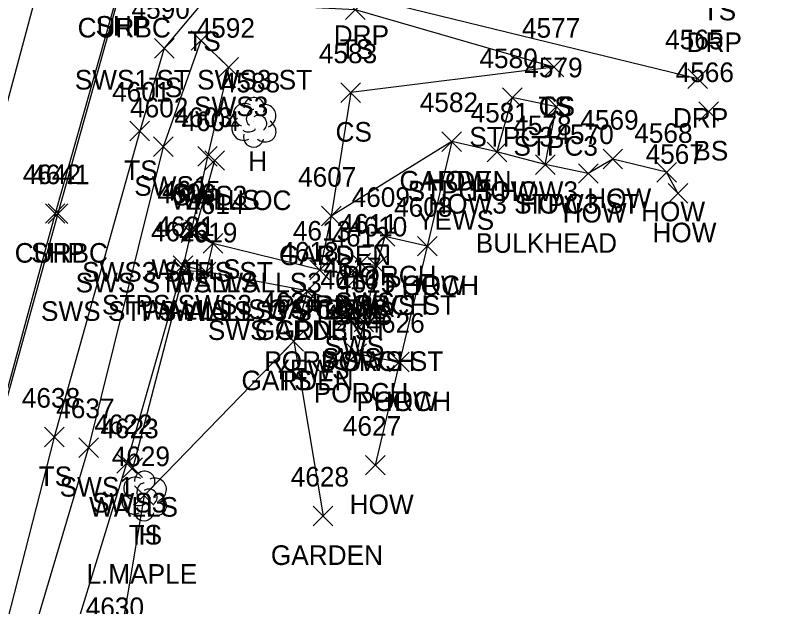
# Model space of a CAD drawing. Extents: x 1443912 to 1445411, y 621446 to 623693.
# Drawn here: x 1444910.4 to 1444988.1, y 623071.7 to 623132 of the extents above; entities that cross this region are included whole.
import ezdxf

# ---------------------------------------------------------------- set-up
doc = ezdxf.new("R2010")
doc.units = 0
for name, color, linetype in [('L_A', 7, 'Continuous'), ('L_C', 7, 'Continuous'), ('L_I', 7, 'Continuous'), ('L_TIC', 7, 'Continuous'), ('LAPB', 7, 'Continuous'), ('LBC', 7, 'Continuous'), ('LBF', 7, 'Continuous'), ('LELB', 7, 'Continuous'), ('LTD', 7, 'Continuous'), ('LWS', 7, 'Continuous'), ('P_A', 7, 'Continuous'), ('P_I', 7, 'Continuous'), ('P_TIC', 7, 'Continuous'), ('PET', 7, 'Continuous'), ('PSP', 7, 'Continuous'), ('R_A', 7, 'Continuous'), ('R_C', 7, 'Continuous'), ('R_I', 7, 'Continuous'), ('R_TIC', 7, 'Continuous'), ('RC', 7, 'Continuous'), ('RDP', 7, 'Continuous'), ('RSW', 7, 'Continuous')]:
    doc.layers.add(name, color=color, linetype=linetype)

msp = doc.modelspace()

# ---------------------------------------------------------------- linework, layer by layer
at = {"layer": 'L_TIC'}
for points in [[(1444944.131, 623131.561), (1444946.131, 623133.561)], [(1444946.131, 623131.561), (1444944.131, 623133.561)], [(1444924.638, 623127.642), (1444926.638, 623129.642)], [(1444926.638, 623127.642), (1444924.638, 623129.642)], [(1444964.389, 623125.715), (1444966.389, 623127.715)], [(1444966.389, 623125.715), (1444964.389, 623127.715)], [(1444964.389, 623125.715), (1444966.389, 623127.715)], [(1444966.389, 623125.715), (1444964.389, 623127.715)], [(1444943.665, 623123.111), (1444945.665, 623125.111)], [(1444945.665, 623123.111), (1444943.665, 623125.111)], [(1444943.665, 623123.111), (1444945.665, 623125.111)], [(1444945.665, 623123.111), (1444943.665, 623125.111)], [(1444960.138, 623122.61), (1444962.138, 623124.61)], [(1444962.138, 623122.61), (1444960.138, 623124.61)], [(1444964.641, 623121.674), (1444966.641, 623123.674)], [(1444966.641, 623121.674), (1444964.641, 623123.674)], [(1444980.176, 623121.189), (1444982.176, 623123.189)], [(1444982.176, 623121.189), (1444980.176, 623123.189)], [(1444922.129, 623119.197), (1444924.129, 623121.197)], [(1444924.129, 623119.197), (1444922.129, 623121.197)], [(1444953.963, 623118.122), (1444955.963, 623120.122)], [(1444955.963, 623118.122), (1444953.963, 623120.122)], [(1444953.963, 623118.122), (1444955.963, 623120.122)], [(1444955.963, 623118.122), (1444953.963, 623120.122)], [(1444958.58, 623117.065), (1444960.58, 623119.065)], [(1444960.58, 623117.065), (1444958.58, 623119.065)], [(1444958.58, 623117.065), (1444960.58, 623119.065)], [(1444960.58, 623117.065), (1444958.58, 623119.065)], [(1444929.77, 623116.189), (1444931.77, 623118.189)], [(1444931.77, 623116.189), (1444929.77, 623118.189)], [(1444970.402, 623116.333), (1444972.402, 623118.333)], [(1444972.402, 623116.333), (1444970.402, 623118.333)], [(1444963.508, 623115.772), (1444965.508, 623117.772)], [(1444965.508, 623115.772), (1444963.508, 623117.772)], [(1444963.508, 623115.772), (1444965.508, 623117.772)], [(1444965.508, 623115.772), (1444963.508, 623117.772)], [(1444967.895, 623114.862), (1444969.895, 623116.862)], [(1444969.895, 623114.862), (1444967.895, 623116.862)], [(1444975.896, 623114.984), (1444977.896, 623116.984)], [(1444977.896, 623114.984), (1444975.896, 623116.984)], [(1444977.054, 623112.845), (1444979.054, 623114.845)], [(1444979.054, 623112.845), (1444977.054, 623114.845)], [(1444941.67, 623110.518), (1444943.67, 623112.518)], [(1444943.67, 623110.518), (1444941.67, 623112.518)], [(1444941.67, 623110.518), (1444943.67, 623112.518)], [(1444943.67, 623110.518), (1444941.67, 623112.518)], [(1444927.357, 623108.831), (1444929.357, 623110.831)], [(1444929.357, 623108.831), (1444927.357, 623110.831)], [(1444927.79, 623109.107), (1444929.79, 623111.107)], [(1444929.79, 623109.107), (1444927.79, 623111.107)], [(1444947.143, 623108.453), (1444949.143, 623110.453)], [(1444949.143, 623108.453), (1444947.143, 623110.453)], [(1444929.602, 623107.733), (1444931.602, 623109.733)], [(1444931.602, 623107.733), (1444929.602, 623109.733)], [(1444929.602, 623107.733), (1444931.602, 623109.733)], [(1444931.602, 623107.733), (1444929.602, 623109.733)], [(1444951.467, 623107.452), (1444953.467, 623109.452)], [(1444953.467, 623107.452), (1444951.467, 623109.452)], [(1444951.467, 623107.452), (1444953.467, 623109.452)], [(1444953.467, 623107.452), (1444951.467, 623109.452)], [(1444926.551, 623105.478), (1444928.551, 623107.478)], [(1444928.551, 623105.478), (1444926.551, 623107.478)], [(1444946.302, 623105.447), (1444948.302, 623107.447)], [(1444948.302, 623105.447), (1444946.302, 623107.447)], [(1444926.665, 623104.942), (1444928.665, 623106.942)], [(1444928.665, 623104.942), (1444926.665, 623106.942)], [(1444928.892, 623104.831), (1444930.892, 623106.831)], [(1444930.892, 623104.831), (1444928.892, 623106.831)], [(1444928.892, 623104.831), (1444930.892, 623106.831)], [(1444930.892, 623104.831), (1444928.892, 623106.831)], [(1444940.493, 623105.02), (1444942.493, 623107.02)], [(1444942.493, 623105.02), (1444940.493, 623107.02)], [(1444939.21, 623102.881), (1444941.21, 623104.881)], [(1444941.21, 623102.881), (1444939.21, 623104.881)], [(1444944.998, 623099.722), (1444946.998, 623101.722)], [(1444946.998, 623099.722), (1444944.998, 623101.722)], [(1444937.841, 623097.754), (1444939.841, 623099.754)], [(1444939.841, 623097.754), (1444937.841, 623099.754)], [(1444937.841, 623097.754), (1444939.841, 623099.754)], [(1444939.841, 623097.754), (1444937.841, 623099.754)], [(1444944.259, 623096.496), (1444946.259, 623098.496)], [(1444946.259, 623096.496), (1444944.259, 623098.496)], [(1444948.621, 623095.625), (1444950.621, 623097.625)], [(1444950.621, 623095.625), (1444948.621, 623097.625)], [(1444948.621, 623095.625), (1444950.621, 623097.625)], [(1444950.621, 623095.625), (1444948.621, 623097.625)], [(1444913.405, 623087.979), (1444915.405, 623089.979)], [(1444915.405, 623087.979), (1444913.405, 623089.979)], [(1444946.162, 623085.114), (1444948.162, 623087.114)], [(1444948.162, 623085.114), (1444946.162, 623087.114)], [(1444921.421, 623084.856), (1444923.421, 623086.856)], [(1444923.421, 623084.856), (1444921.421, 623086.856)], [(1444922.581, 623082.015), (1444924.581, 623084.015)], [(1444924.581, 623082.015), (1444922.581, 623084.015)], [(1444940.841, 623079.933), (1444942.841, 623081.933)], [(1444942.841, 623079.933), (1444940.841, 623081.933)]]:
    msp.add_lwpolyline(points, dxfattribs=at)
at = {"layer": 'LAPB'}
for points in [[(1444954.963, 623119.122), (1444942.67, 623111.518), (1444941.493, 623106.02)], [(1444940.21, 623103.881), (1444938.841, 623098.754), (1444941.841, 623080.933)]]:
    msp.add_lwpolyline(points, dxfattribs=at)
at = {"layer": 'LBC'}
msp.add_lwpolyline([(1444978.054, 623113.845), (1444976.896, 623115.984), (1444971.402, 623117.333), (1444968.895, 623115.862), (1444964.508, 623116.772), (1444959.58, 623118.065), (1444954.963, 623119.122), (1444952.467, 623108.452), (1444949.621, 623096.625), (1444947.162, 623086.114)], dxfattribs=at)
at = {"layer": 'LBF'}
for points in [[(1444964.508, 623116.772), (1444965.641, 623122.674), (1444961.138, 623123.61), (1444959.58, 623118.065)], [(1444928.357, 623109.831), (1444930.602, 623108.733), (1444929.892, 623105.831), (1444927.551, 623106.478)], [(1444952.467, 623108.452), (1444948.143, 623109.453), (1444947.302, 623106.447), (1444945.998, 623100.722), (1444945.259, 623097.496), (1444949.621, 623096.625)]]:
    msp.add_lwpolyline(points, dxfattribs=at)
at = {"layer": 'LELB'}
for points in [[(1444965.389, 623126.715), (1444945.131, 623132.561), (1444929.57, 623133.35), (1444925.638, 623128.642), (1444923.129, 623120.197), (1444914.405, 623088.979), (1444907.699, 623062.922), (1444896.39, 623030.415), (1444888.476, 622997.96), (1444877.452, 622951.177), (1444886.066, 622942.698), (1444898.812, 622937.039), (1444925.542, 622926.459)], [(1444965.389, 623126.715), (1444944.665, 623124.111)], [(1444944.665, 623124.111), (1444942.67, 623111.518)], [(1444938.841, 623098.754), (1444923.581, 623083.015), (1444921.009, 623067.619), (1444940.194, 623059.275), (1444959.418, 623058.381)]]:
    msp.add_lwpolyline(points, dxfattribs=at)
at = {"layer": 'LTD'}
for p, q in [((1444934.761, 623121.131), (1444934.761, 623121.131)), ((1444934.761, 623121.131), (1444934.761, 623121.131)), ((1444923.581, 623083.015), (1444923.581, 623083.015)), ((1444923.581, 623083.015), (1444923.581, 623083.015))]:
    msp.add_line(p, q, dxfattribs=at)
for centre in [(1444934.808, 623122.565), (1444923.628, 623084.449)]:
    msp.add_arc(centre, 1.047, 335.52715, 180.95627, dxfattribs=at)
for centre, major_axis, ratio, start_param, end_param in [((1444933.969, 623121.798), (1.21, -0.512), 0.895232, 1.570796, 4.712389), ((1444935.803, 623121.715), (-1.141, -0.483), 0.949671, 1.570796, 4.712389), ((1444934.553, 623121.589), (-0.208, -0.792), 0.645439, 3.141593, 6.283185), ((1444933.678, 623120.423), (0.584, -1.042), 0.959034, 3.141593, 6.283185), ((1444935.261, 623120.964), (-0.5, 0.667), 0.989748, 3.141593, 6.283185), ((1444934.303, 623120.381), (-0.625, -0.083), 0.423636, 0, 3.141593), ((1444935.761, 623120.298), (-1.09, 0.792), 0.841452, 1.570796, 4.712389), ((1444934.761, 623119.631), (0.265, 1.061), 0.942809, 1.570796, 4.712389), ((1444922.79, 623083.681), (1.21, -0.512), 0.895232, 1.570796, 4.712389), ((1444924.623, 623083.598), (-1.141, -0.483), 0.949671, 1.570796, 4.712389), ((1444923.373, 623083.473), (-0.208, -0.792), 0.645439, 3.141593, 6.283185), ((1444922.498, 623082.306), (0.584, -1.042), 0.959034, 3.141593, 6.283185), ((1444924.082, 623082.848), (-0.5, 0.667), 0.989748, 3.141593, 6.283185), ((1444924.582, 623082.181), (-1.09, 0.792), 0.841452, 1.570796, 4.712389), ((1444923.582, 623081.515), (0.265, 1.061), 0.942809, 1.570796, 4.712389), ((1444923.123, 623082.265), (-0.625, -0.083), 0.423636, 0, 3.141593)]:
    msp.add_ellipse(centre, major_axis=major_axis, ratio=ratio, start_param=start_param, end_param=end_param, dxfattribs=at)
at = {"layer": 'LWS'}
for points in [[(1444930.77, 623117.189), (1444928.79, 623110.107), (1444930.602, 623108.733)], [(1444929.892, 623105.831), (1444927.665, 623105.942), (1444922.421, 623085.856)]]:
    msp.add_lwpolyline(points, dxfattribs=at)
at = {"layer": 'P_TIC'}
for points in [[(1444913.496, 623110.784), (1444915.496, 623112.784)], [(1444915.496, 623110.784), (1444913.496, 623112.784)]]:
    msp.add_lwpolyline(points, dxfattribs=at)
at = {"layer": 'PET'}
msp.add_lwpolyline([(1445060.037, 623670.522), (1445049.49, 623631.423), (1445031.605, 623567.438), (1445020.437, 623527.05), (1445003.496, 623465.591), (1444988.101, 623409.137), (1444976.63, 623367.032), (1444962.485, 623315.052), (1444949.489, 623267.355), (1444937.78, 623225.39), (1444926.085, 623182.222), (1444915.481, 623145.054), (1444906.981, 623113.479), (1444893.635, 623066.096), (1444886.059, 623037.306), (1444876.58, 623001.084), (1444863.334, 622947.053), (1444849.426, 622890.74)], dxfattribs=at)
at = {"layer": 'PSP'}
msp.add_lwpolyline([(1444984.516, 623364.945), (1444970.172, 623313.004), (1444960.845, 623279.611), (1444959.914, 623275.87), (1444955.536, 623257.941), (1444945.503, 623223.598), (1444933.942, 623181.42), (1444927.821, 623159.658), (1444926.956, 623156.444), (1444922.102, 623137.709), (1444921.079, 623134.92), (1444914.496, 623111.784), (1444901.392, 623063.858), (1444892.119, 623031.221), (1444883.166, 622999.191), (1444870.024, 622952.196), (1444868.676, 622947.266), (1444864.214, 622931.668)], dxfattribs=at)
at = {"layer": 'R_TIC'}
for points in [[(1444928.375, 623128.426), (1444930.375, 623130.426)], [(1444930.375, 623128.426), (1444928.375, 623130.426)], [(1444928.375, 623128.426), (1444930.375, 623130.426)], [(1444930.375, 623128.426), (1444928.375, 623130.426)], [(1444931.196, 623125.709), (1444933.196, 623127.709)], [(1444933.196, 623125.709), (1444931.196, 623127.709)], [(1444979.049, 623124.529), (1444981.049, 623126.529)], [(1444981.049, 623124.529), (1444979.049, 623126.529)], [(1444924.529, 623117.588), (1444926.529, 623119.588)], [(1444926.529, 623117.588), (1444924.529, 623119.588)], [(1444929.042, 623116.605), (1444931.042, 623118.605)], [(1444931.042, 623116.605), (1444929.042, 623118.605)], [(1444913.787, 623110.766), (1444915.787, 623112.766)], [(1444915.787, 623110.766), (1444913.787, 623112.766)], [(1444927.357, 623108.831), (1444929.357, 623110.831)], [(1444929.357, 623108.831), (1444927.357, 623110.831)], [(1444929.602, 623107.733), (1444931.602, 623109.733)], [(1444931.602, 623107.733), (1444929.602, 623109.733)], [(1444926.551, 623105.478), (1444928.551, 623107.478)], [(1444928.551, 623105.478), (1444926.551, 623107.478)], [(1444944.676, 623105.727), (1444946.676, 623107.727)], [(1444946.676, 623105.727), (1444944.676, 623107.727)], [(1444946.302, 623105.447), (1444948.302, 623107.447)], [(1444948.302, 623105.447), (1444946.302, 623107.447)], [(1444928.892, 623104.831), (1444930.892, 623106.831)], [(1444930.892, 623104.831), (1444928.892, 623106.831)], [(1444940.493, 623105.02), (1444942.493, 623107.02)], [(1444942.493, 623105.02), (1444940.493, 623107.02)], [(1444944.427, 623104.407), (1444946.427, 623106.407)], [(1444946.427, 623104.407), (1444944.427, 623106.407)], [(1444939.21, 623102.881), (1444941.21, 623104.881)], [(1444941.21, 623102.881), (1444939.21, 623104.881)], [(1444943.607, 623101.283), (1444945.607, 623103.283)], [(1444945.607, 623101.283), (1444943.607, 623103.283)], [(1444943.359, 623100.046), (1444945.359, 623102.046)], [(1444945.359, 623100.046), (1444943.359, 623102.046)], [(1444944.998, 623099.722), (1444946.998, 623101.722)], [(1444946.998, 623099.722), (1444944.998, 623101.722)], [(1444916.914, 623086.903), (1444918.914, 623088.903)], [(1444918.914, 623086.903), (1444916.914, 623088.903)], [(1444920.794, 623085.282), (1444922.794, 623087.282)], [(1444922.794, 623085.282), (1444920.794, 623087.282)]]:
    msp.add_lwpolyline(points, dxfattribs=at)
at = {"layer": 'RC'}
msp.add_lwpolyline([(1444922.102, 623137.709), (1444921.209, 623134.736), (1444914.787, 623111.766), (1444901.487, 623063.724), (1444892.451, 623031.114), (1444883.386, 622999.316), (1444870.3, 622952.188), (1444868.676, 622947.266)], dxfattribs=at)
at = {"layer": 'RDP'}
msp.add_lwpolyline([(1444980.049, 623125.529), (1444945.435, 623133.975), (1444929.755, 623137.061), (1444922.102, 623137.709)], dxfattribs=at)
at = {"layer": 'RSW'}
for points in [[(1444929.375, 623129.426), (1444925.529, 623118.588), (1444917.914, 623087.903), (1444910.406, 623062.752), (1444901.174, 623028.613), (1444893.173, 623000.339)], [(1444929.375, 623129.426), (1444932.196, 623126.709), (1444930.042, 623117.605), (1444928.357, 623109.831), (1444927.551, 623106.478), (1444921.794, 623086.282), (1444913.795, 623060.309), (1444904.864, 623027.17), (1444897.167, 622999.119), (1444893.173, 623000.339)], [(1444947.302, 623106.447), (1444945.676, 623106.727), (1444945.427, 623105.407), (1444941.493, 623106.02), (1444930.602, 623108.733)], [(1444945.998, 623100.722), (1444944.359, 623101.046), (1444944.607, 623102.283), (1444940.21, 623103.881), (1444929.892, 623105.831)]]:
    msp.add_lwpolyline(points, dxfattribs=at)

# ---------------------------------------------------------------- texts
at = {"layer": 'L_A'}
for s, p in [('TS', (1444980.57, 623131.484)), ('TS', (1444927.98, 623128.35)), ('TS', (1444943.541, 623127.561)), ('TS', (1444924.048, 623123.642)), ('TS', (1444963.798, 623121.715)), ('CS', (1444963.83, 623121.715)), ('CS', (1444943.106, 623119.111)), ('CS', (1444943.106, 623119.111)), ('STPC3', (1444956.76, 623118.61)), ('STPC3', (1444961.263, 623117.674)), ('BS', (1444979.617, 623117.189)), ('H', (1444934.194, 623116.131)), ('TS', (1444921.538, 623115.197)), ('GARDEN', (1444949.633, 623114.122)), ('HOW', (1444952.349, 623114.122)), ('STPC3 HOW3', (1444950.462, 623113.065)), ('HOW', (1444956.966, 623113.065)), ('HOW', (1444968.787, 623112.333)), ('WALLS', (1444926.313, 623112.189)), ('HOW3 STPC3 ST', (1444952.564, 623111.772)), ('HOW', (1444961.894, 623111.772)), ('HOW', (1444966.281, 623110.862)), ('HOW', (1444974.282, 623110.984)), ('HOW', (1444975.44, 623108.845)), ('GARDEN', (1444937.339, 623106.518)), ('CS', (1444941.111, 623106.518)), ('SWS3 STPS ST', (1444917.246, 623104.831)), ('WALLS', (1444924.334, 623105.107)), ('PORCH', (1444943.765, 623104.453)), ('SWS STPS WALLS3', (1444916.587, 623103.733)), ('WALLS', (1444926.146, 623103.733)), ('PORCH', (1444948.089, 623103.452)), ('HOW', (1444949.852, 623103.452)), ('STPS SWS3', (1444919.268, 623101.478)), ('PORCH', (1444942.924, 623101.447)), ('SWS STPS WALLS3 ST', (1444913.05, 623100.831)), ('WALLS', (1444923.208, 623100.942)), ('WALLS', (1444925.436, 623100.831)), ('GARDEN', (1444936.162, 623101.02)), ('GARDEN', (1444934.88, 623098.881)), ('PORCH', (1444941.62, 623095.722)), ('GARDEN', (1444933.51, 623093.754)), ('TS', (1444937.25, 623093.754)), ('PORCH', (1444940.881, 623092.496)), ('PORCH', (1444945.243, 623091.625)), ('HOW', (1444947.007, 623091.625)), ('TS', (1444912.814, 623083.979)), ('WALLS', (1444917.965, 623080.856)), ('HOW', (1444944.548, 623081.114)), ('TS', (1444921.991, 623078.015)), ('H', (1444923.015, 623078.015)), ('GARDEN', (1444936.51, 623075.933))]:
    msp.add_text(s, height=2, dxfattribs=at).set_placement(p)
at = {"layer": 'L_C'}
for s, p in [('L.LOC', (1444930.879, 623112.131)), ('YEWS', (1444951.42, 623110.122)), ('BULKHEAD', (1444957.414, 623107.772)), ('L.MAPLE', (1444917.692, 623074.015))]:
    msp.add_text(s, height=2, dxfattribs=at).set_placement(p)
at = {"layer": 'L_I'}
for s, p in [('4590', (1444922.292, 623131.642)), ('4577', (1444962.129, 623129.715)), ('4577', (1444962.129, 623129.715)), ('4583', (1444941.406, 623127.111)), ('4583', (1444941.406, 623127.111)), ('4580', (1444957.792, 623126.61)), ('4579', (1444962.373, 623125.674)), ('4566', (1444977.813, 623125.189)), ('4588', (1444931.501, 623124.131)), ('4601', (1444920.31, 623123.197)), ('4582', (1444951.704, 623122.122)), ('4582', (1444951.704, 623122.122)), ('4581', (1444956.887, 623121.065)), ('4581', (1444956.887, 623121.065)), ('4604', (1444927.384, 623120.189)), ('4569', (1444968.087, 623120.333)), ('4578', (1444961.249, 623119.772)), ('4578', (1444961.249, 623119.772)), ('4570', (1444965.548, 623118.862)), ('4568', (1444973.589, 623118.984)), ('4567', (1444974.747, 623116.845)), ('4607', (1444939.284, 623114.518)), ('4607', (1444939.284, 623114.518)), ('4605', (1444925.405, 623113.107)), ('4606', (1444924.916, 623112.831)), ('4609', (1444944.75, 623112.453)), ('4614', (1444927.862, 623111.733)), ('4614', (1444927.862, 623111.733)), ('4608', (1444949.081, 623111.452)), ('4608', (1444949.081, 623111.452)), ('4621', (1444924.811, 623109.478)), ('4610', (1444944.476, 623109.447)), ('4620', (1444924.271, 623108.942)), ('4619', (1444927.144, 623108.831)), ('4619', (1444927.144, 623108.831)), ('4613', (1444938.753, 623109.02)), ('4618', (1444937.47, 623106.881)), ('4615', (1444943.258, 623103.722)), ('4624', (1444935.534, 623101.754)), ('4624', (1444935.534, 623101.754)), ('4625', (1444941.952, 623100.496)), ('4626', (1444946.259, 623099.625)), ('4626', (1444946.259, 623099.625)), ('4638', (1444911.098, 623091.979)), ('4627', (1444943.855, 623089.114)), ('4623', (1444919.114, 623088.856)), ('4629', (1444920.267, 623086.015)), ('4629', (1444920.267, 623086.015)), ('4628', (1444938.534, 623083.933)), ('4630', (1444917.615, 623070.619))]:
    msp.add_text(s, height=2, dxfattribs=at).set_placement(p)
at = {"layer": 'P_A'}
for p in [(1444918.615, 623129.92), (1444912.031, 623106.784)]:
    msp.add_text('SHP', height=2, dxfattribs=at).set_placement(p)
at = {"layer": 'P_I'}
msp.add_text('4642', height=2, dxfattribs=at).set_placement((1444911.189, 623114.784))
at = {"layer": 'R_A'}
for s, p in [('CURBC', (1444916.792, 623129.736)), ('DRP', (1444942.923, 623128.975)), ('DRP', (1444978.933, 623128.249)), ('SWS1 ST SWS3 ST', (1444916.501, 623124.426)), ('SWS1 ST SWS3 ST', (1444916.501, 623124.426)), ('SWS3', (1444928.668, 623121.709)), ('DRP', (1444977.537, 623120.529)), ('SWS1', (1444922.569, 623113.588)), ('SWS3', (1444926.515, 623112.605)), ('CURBC', (1444910.37, 623106.766)), ('SWS3 STPS ST', (1444917.246, 623104.831)), ('SWS STPS WALLS3', (1444916.587, 623103.733)), ('STPS SWS3', (1444919.268, 623101.478)), ('POR3 SWS ST', (1444937.137, 623101.447)), ('SWS', (1444943.047, 623101.727)), ('SWS STPS WALLS3 ST', (1444913.05, 623100.831)), ('SWS GDN3', (1444934.186, 623101.02)), ('SWS', (1444942.797, 623100.407)), ('SWS GDN3 ST', (1444930.076, 623098.881)), ('SWS', (1444941.977, 623097.283)), ('SWS', (1444941.729, 623096.046)), ('POR3 SWS ST', (1444935.833, 623095.722)), ('SWS1', (1444914.954, 623082.903)), ('SWS3', (1444918.266, 623081.282))]:
    msp.add_text(s, height=2, dxfattribs=at).set_placement(p)
at = {"layer": 'R_C'}
msp.add_text('YEWS', height=2, dxfattribs=at).set_placement((1444936.667, 623094.881))
at = {"layer": 'R_I'}
for s, p in [('4592', (1444928.936, 623129.709)), ('4565', (1444976.742, 623128.529)), ('4602', (1444922.143, 623121.588)), ('4603', (1444926.656, 623120.605)), ('4641', (1444912.047, 623114.766)), ('4606', (1444924.916, 623112.831)), ('4614', (1444927.862, 623111.733)), ('4621', (1444924.811, 623109.478)), ('4611', (1444943.503, 623109.727)), ('4610', (1444944.476, 623109.447)), ('4619', (1444927.144, 623108.831)), ('4613', (1444938.753, 623109.02)), ('4612', (1444942.687, 623108.407)), ('4618', (1444937.47, 623106.881)), ('4617', (1444941.867, 623105.283)), ('4616', (1444941.564, 623104.046)), ('4615', (1444943.258, 623103.722)), ('4637', (1444914.607, 623090.903)), ('4622', (1444918.487, 623089.282))]:
    msp.add_text(s, height=2, dxfattribs=at).set_placement(p)

doc.saveas('drawing.dxf')
